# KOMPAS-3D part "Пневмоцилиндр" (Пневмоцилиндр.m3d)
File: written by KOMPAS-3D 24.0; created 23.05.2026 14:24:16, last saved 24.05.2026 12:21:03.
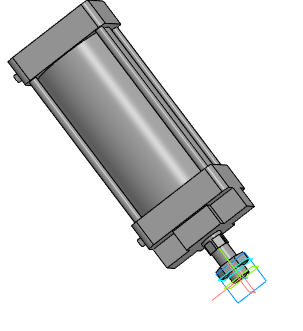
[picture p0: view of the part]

Document properties: Автор: R2D2; Полное имя файла: E:\Работа\Зайцев\GVKR1331E-1W-Fb-2P Задвижка шиберная DN.ru Ду50-300 Ру16-10-6\исходные материалы\DN150\Пневмоцилиндр.m3d

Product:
- Part/product: Пневмоцилиндр
    Масса: 39.90479

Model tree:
1. Эскиз:1
2. Элемент выдавливания:1
3. Смещенная плоскость:1
4. Эскиз:2
5. Элемент выдавливания:2
6. Эскиз:3  (with: Грань.Элемент выдавливания:1)
7. Элемент выдавливания:3
     Расстояние 1 = 3.29033e-05
8. Эскиз:4  (with: Грань.Элемент выдавливания:3)
9. Элемент выдавливания:4  (with: Грань.Элемент выдавливания:3)
     Расстояние 2 = 15; Смещение 2 = 5
10. Эскиз:5  (with: Грань.Элемент выдавливания:3)
11. Элемент выдавливания:5
     Расстояние 1 = 141320
12. Эскиз:6  (with: Грань.Элемент выдавливания:5)
13. Элемент выдавливания:6
14. Эскиз:7  (with: Грань.Элемент выдавливания:6)
15. Элемент выдавливания:7
16. Эскиз:8  (with: Грань.Элемент выдавливания:7, Ребро.Элемент выдавливания:6)
17. Элемент выдавливания:8
18. Эскиз:9  (with: Грань.Элемент выдавливания:6, Вершина.Элемент выдавливания:8)
19. Элемент выдавливания:9  (with: Грань.Элемент выдавливания:8)
     Расстояние 1 = 244
20. Массив по концентрической сетке:1  (with: Элемент выдавливания:9, Эскиз:9)  (4 pattern instances)
     Шаг 2 = 360
21. Скругление:1  (with: Ребро.Элемент выдавливания:6, Ребро.Элемент выдавливания:8)
     Радиус = 10
22. Эскиз:10  (with: Грань.Элемент выдавливания:5, Ребро.Элемент выдавливания:6, Ребро.Элемент выдавливания:8)
23. Элемент выдавливания:10
24. Эскиз:11  (with: Грань.Элемент выдавливания:5, Ребро.Элемент выдавливания:10)
25. Элемент выдавливания:11
26. Эскиз:12  (with: Ребро.Элемент выдавливания:6, Ребро.Элемент выдавливания:5)
27. Элемент выдавливания:12

Expressions: k/2; c-2*g+x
